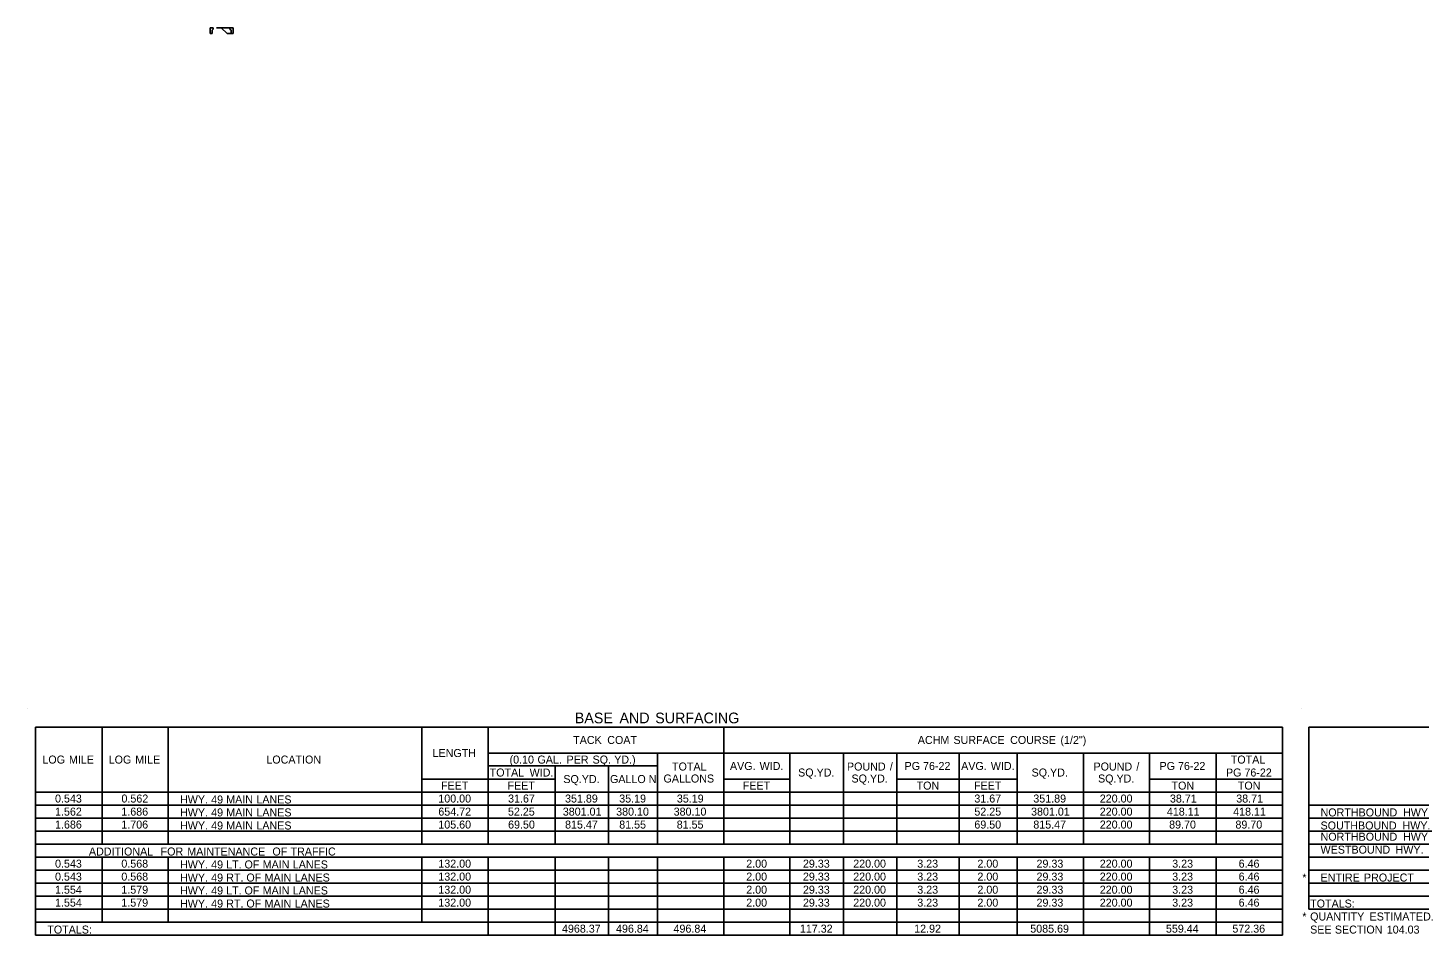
# Model space of a CAD drawing. Extents: x 107 to 7866, y 32 to 1473.
# Drawn here: x 2166 to 3209, y 716 to 1396 of the extents above; entities that cross this region are included whole.
import ezdxf

# ---------------------------------------------------------------- set-up
doc = ezdxf.new("R2010")
doc.units = 0
doc.layers.add('Default', color=7, linetype='Continuous')
doc.layers.add('R_No Plot', color=7, linetype='Continuous')

msp = doc.modelspace()

# ---------------------------------------------------------------- linework, layer by layer
at = {"layer": 'Default'}
for p, q in [((2166.5, 885.8), (2166.5, 885.8)), ((3120.9, 885.8), (3120.9, 885.8)), ((2172.3, 872.1), (3106.9, 872.1)), ((2172.3, 716.1), (2172.3, 872.1)), ((2172.3, 716.1), (2172.3, 872.1)), ((2222.1, 784.4), (2222.1, 872.1)), ((2271.8, 784.4), (2271.8, 872.1)), ((2271.8, 784.4), (2271.8, 872.1)), ((2461.9, 784.4), (2461.9, 872.1)), ((2511.6, 784.4), (2511.6, 872.1)), ((2688.1, 784.4), (2688.1, 872.1)), ((3106.9, 716.1), (3106.9, 872.1)), ((3126.7, 872.1), (3713.7, 872.1)), ((3126.7, 735.6), (3126.7, 872.1)), ((3126.7, 735.6), (3126.7, 872.1)), ((2511.6, 852.6), (3106.9, 852.6)), ((2638.4, 784.4), (2638.4, 852.6)), ((2737.8, 852.6), (2777.8, 852.6)), ((2737.8, 784.4), (2737.8, 852.6)), ((2777.8, 784.4), (2777.8, 852.6)), ((2817.8, 784.4), (2817.8, 852.6)), ((2864.6, 784.4), (2864.6, 852.6)), ((2908, 852.6), (2957.7, 852.6)), ((2908, 784.4), (2908, 852.6)), ((2957.7, 784.4), (2957.7, 852.6)), ((3007.4, 784.4), (3007.4, 852.6)), ((3057.2, 784.4), (3057.2, 852.6)), ((3106.9, 784.4), (3106.9, 852.6)), ((2511.6, 842.9), (2638.4, 842.9)), ((2561.9, 784.4), (2561.9, 842.9)), ((2601.8, 784.4), (2601.8, 842.9)), ((2461.9, 833.1), (2561.9, 833.1)), ((2511.6, 784.4), (2511.6, 833.1)), ((2561.9, 784.4), (2561.9, 833.1)), ((2688.1, 833.1), (2737.8, 833.1)), ((2688.1, 784.4), (2688.1, 833.1)), ((2737.8, 784.4), (2737.8, 833.1)), ((2817.8, 833.1), (2908, 833.1)), ((2864.6, 784.4), (2864.6, 833.1)), ((2908, 784.4), (2908, 833.1)), ((3007.4, 833.1), (3106.9, 833.1)), ((2172.3, 823.4), (3106.9, 823.4)), ((2172.3, 813.6), (3106.9, 813.6)), ((2222.1, 784.4), (2222.1, 823.4)), ((2461.9, 784.4), (2461.9, 823.4)), ((2561.9, 823.4), (2601.8, 823.4)), ((2601.8, 823.4), (2737.8, 823.4)), ((2601.8, 784.4), (2601.8, 823.4)), ((2638.4, 784.4), (2638.4, 823.4)), ((2737.8, 823.4), (2908, 823.4)), ((2777.8, 784.4), (2777.8, 823.4)), ((2817.8, 784.4), (2817.8, 823.4)), ((2908, 823.4), (3106.9, 823.4)), ((2957.7, 784.4), (2957.7, 823.4)), ((3007.4, 784.4), (3007.4, 823.4)), ((3057.2, 784.4), (3057.2, 823.4)), ((3126.7, 813.6), (3713.7, 813.6)), ((2172.3, 803.9), (3106.9, 803.9)), ((3126.7, 803.9), (3713.7, 803.9)), ((2172.3, 794.1), (3106.9, 794.1)), ((3126.7, 794.1), (3713.7, 794.1)), ((2172.3, 784.4), (2561.9, 784.4)), ((2172.3, 784.4), (3106.9, 784.4)), ((2561.9, 784.4), (2688.1, 784.4)), ((2688.1, 784.4), (2908, 784.4)), ((2908, 784.4), (2957.7, 784.4)), ((2957.7, 784.4), (3057.2, 784.4)), ((3057.2, 784.4), (3106.9, 784.4)), ((3126.7, 784.4), (3713.7, 784.4)), ((2172.3, 774.6), (3106.9, 774.6)), ((2222.1, 725.9), (2222.1, 774.6)), ((2222.1, 725.9), (2222.1, 774.6)), ((2271.8, 725.9), (2271.8, 774.6)), ((2271.8, 725.9), (2271.8, 774.6)), ((2461.9, 725.9), (2461.9, 774.6)), ((2461.9, 725.9), (2461.9, 774.6)), ((2511.6, 716.1), (2511.6, 774.6)), ((2511.6, 716.1), (2511.6, 774.6)), ((2561.9, 716.1), (2561.9, 774.6)), ((2561.9, 716.1), (2561.9, 774.6)), ((2601.8, 725.9), (2601.8, 774.6)), ((2601.8, 716.1), (2601.8, 774.6)), ((2638.4, 725.9), (2638.4, 774.6)), ((2638.4, 716.1), (2638.4, 774.6)), ((2688.1, 716.1), (2688.1, 774.6)), ((2688.1, 716.1), (2688.1, 774.6)), ((2737.8, 716.1), (2737.8, 774.6)), ((2737.8, 716.1), (2737.8, 774.6)), ((2777.8, 716.1), (2777.8, 774.6)), ((2777.8, 716.1), (2777.8, 774.6)), ((2817.8, 716.1), (2817.8, 774.6)), ((2817.8, 716.1), (2817.8, 774.6)), ((2864.6, 716.1), (2864.6, 774.6)), ((2864.6, 716.1), (2864.6, 774.6)), ((2908, 716.1), (2908, 774.6)), ((2908, 716.1), (2908, 774.6)), ((2957.7, 716.1), (2957.7, 774.6)), ((2957.7, 716.1), (2957.7, 774.6)), ((3007.4, 716.1), (3007.4, 774.6)), ((3007.4, 716.1), (3007.4, 774.6)), ((3057.2, 716.1), (3057.2, 774.6)), ((3057.2, 716.1), (3057.2, 774.6)), ((3106.9, 716.1), (3106.9, 774.6)), ((3126.7, 774.6), (3713.7, 774.6)), ((2172.3, 764.9), (3106.9, 764.9)), ((3126.7, 764.9), (3713.7, 764.9)), ((2172.3, 755.1), (3106.9, 755.1)), ((3126.7, 755.1), (3713.7, 755.1)), ((2172.3, 745.4), (3106.9, 745.4)), ((3126.7, 745.4), (3713.7, 745.4)), ((2172.3, 735.6), (3106.9, 735.6)), ((3126.7, 735.6), (3713.7, 735.6)), ((2172.3, 725.9), (3106.9, 725.9)), ((2172.3, 716.1), (3106.9, 716.1))]:
    msp.add_line(p, q, dxfattribs=at)
at = {"layer": 'R_No Plot'}
for p, q in [((2303.2, 1396.1), (2305.5, 1396.1)), ((2303.2, 1396.1), (2303.2, 1394.3)), ((2303.2, 1394.3), (2303.2, 1391.7)), ((2303.2, 1391.7), (2304.7, 1391.7)), ((2304.7, 1394.3), (2305.5, 1395.1)), ((2304.7, 1391.7), (2304.7, 1394.3)), ((2305.5, 1396.1), (2305.5, 1395.1)), ((2320.3, 1396.1), (2307.9, 1396.1)), ((2315.8, 1391.7), (2311.4, 1396.1)), ((2318.8, 1391.7), (2315.8, 1391.7)), ((2318, 1396.1), (2318, 1395.1)), ((2318.8, 1394.3), (2318, 1395.1)), ((2318.8, 1391.7), (2318.8, 1394.3)), ((2320.3, 1391.7), (2318.8, 1391.7)), ((2320.3, 1396.1), (2320.3, 1394.3)), ((2320.3, 1394.3), (2320.3, 1391.7))]:
    msp.add_line(p, q, dxfattribs=at)
msp.add_lwpolyline([(2315.8, 1391.7), (2311.4, 1396.1), (2318, 1396.1), (2318, 1395.1), (2318.8, 1394.3), (2318.8, 1391.7)], close=True, dxfattribs=at)

# ---------------------------------------------------------------- texts
at = {"layer": 'Default'}
for s, height, p in [('BASE', 8, (2576.5, 874.9)), (' AND', 8, (2607, 874.9)), (' SURFACING', 8, (2633.8, 874.9)), (' (1/2")', 6, (2938.3, 859.4)), ('LENGTH', 6, (2469.9, 849.6)), ('TACK', 6, (2575.3, 859.4)), (' COAT', 6, (2598.6, 859.4)), ('ACHM', 6, (2833.6, 859.4)), (' SURFACE', 6, (2858.1, 859.4)), (' COURSE', 6, (2900.6, 859.4)), ('LOG', 6, (2177.4, 844.7)), (' MILE', 6, (2195.1, 844.7)), ('LOG', 6, (2227.1, 844.7)), (' MILE', 6, (2244.8, 844.7)), ('LOCATION', 6, (2345.3, 844.7)), ('(0.10', 6, (2527.6, 844.7)), (' GAL.', 6, (2546.3, 844.7)), (' PER', 6, (2568.1, 844.7)), (' SQ.', 6, (2587.6, 844.7)), (' YD.)', 6, (2603.8, 844.7)), ('TOTAL', 6, (2649.4, 839.5)), ('AVG.', 6, (2692.8, 839.9)), (' WID.', 6, (2712.8, 839.9)), ('POUND', 6, (2780.5, 839.5)), (' /', 6, (2810.4, 839.5)), ('PG', 6, (2823.7, 839.9)), (' 76-22', 6, (2835.3, 839.9)), ('AVG.', 6, (2866.1, 839.9)), (' WID.', 6, (2886.1, 839.9)), ('POUND', 6, (2965.3, 839.5)), (' /', 6, (2995.2, 839.5)), ('PG', 6, (3014.8, 839.9)), (' 76-22', 6, (3026.4, 839.9)), ('TOTAL', 6, (3068.2, 844.7)), ('TOTAL', 6, (2512.7, 835)), (' WID.', 6, (2540.4, 835)), ('SQ.YD.', 6, (2567.9, 830.1)), ('GALLO', 6, (2602.9, 830.1)), ('N', 6, (2631.9, 830.1)), ('GALLONS', 6, (2643, 830.5)), ('SQ.YD.', 6, (2743.9, 835)), ('SQ.YD.', 6, (2783.9, 830.5)), ('SQ.YD.', 6, (2918.9, 835)), ('SQ.YD.', 6, (2968.7, 830.5)), ('PG', 6, (3064.6, 835)), (' 76-22', 6, (3076.2, 835)), ('FEET', 6, (2476.2, 825.2)), ('FEET', 6, (2526.1, 825.2)), ('FEET', 6, (2702.4, 825.2)), ('TON', 6, (2832.7, 825.2)), ('FEET', 6, (2875.7, 825.2)), ('TON', 6, (3023.8, 825.2)), ('TON', 6, (3073.5, 825.2)), ('0.543', 6, (2186.9, 815.5)), ('0.562', 6, (2236.7, 815.5)), ('HWY.', 6, (2280.6, 814.8)), (' 49', 6, (2301.7, 814.8)), (' MAIN', 6, (2313, 814.8)), (' LANES', 6, (2335.6, 814.8)), ('100.00', 6, (2474.2, 815.5)), ('31.67', 6, (2526.5, 815.5)), ('351.89', 6, (2569.2, 815.5)), ('35.19', 6, (2609.8, 815.5)), ('35.19', 6, (2653, 815.5)), ('31.67', 6, (2876, 815.5)), ('351.89', 6, (2920.2, 815.5)), ('220.00', 6, (2970, 815.5)), ('38.71', 6, (3022.6, 815.5)), ('38.71', 6, (3072.3, 815.5)), ('1.562', 6, (2186.9, 805.7)), ('1.686', 6, (2236.6, 805.7)), ('HWY.', 6, (2280.6, 805.1)), (' 49', 6, (2301.7, 805.1)), (' MAIN', 6, (2313, 805.1)), (' LANES', 6, (2335.6, 805.1)), ('654.72', 6, (2474.2, 805.7)), ('52.25', 6, (2526.4, 805.7)), ('3801.01', 6, (2567.5, 805.7)), ('380.10', 6, (2607.5, 805.7)), ('380.10', 6, (2650.6, 805.7)), ('52.25', 6, (2876, 805.7)), ('3801.01', 6, (2918.5, 805.7)), ('220.00', 6, (2970, 805.7)), ('418.11', 6, (3020.3, 805.7)), ('418.11', 6, (3070, 805.7)), ('NORTHBOUND', 6, (3135.5, 805.1)), (' HWY.', 6, (3195.1, 805.1)), ('1.686', 6, (2186.9, 796)), ('1.706', 6, (2236.6, 796)), ('HWY.', 6, (2280.6, 795.3)), (' 49', 6, (2301.7, 795.3)), (' MAIN', 6, (2313, 795.3)), (' LANES', 6, (2335.6, 795.3)), ('105.60', 6, (2474.2, 796)), ('69.50', 6, (2526.5, 796)), ('815.47', 6, (2569.2, 796)), ('81.55', 6, (2609.8, 796)), ('81.55', 6, (2652.9, 796)), ('69.50', 6, (2876, 796)), ('815.47', 6, (2920.2, 796)), ('220.00', 6, (2970, 796)), ('89.70', 6, (3022, 796)), ('89.70', 6, (3071.7, 796)), ('SOUTHBOUND', 6, (3135.5, 795.3)), ('NORTHBOUND', 6, (3135.5, 786.9)), (' HWY.', 6, (3194.7, 795.3)), (' HWY.', 6, (3195.1, 786.9)), ('WESTBOUND', 6, (3135.5, 777.2)), (' HWY.', 6, (3189.5, 777.2)), ('0.543', 6, (2186.9, 766.7)), ('ADDITIONAL', 6, (2212.3, 775.8)), ('0.568', 6, (2236.6, 766.7)), (' FOR', 6, (2263.8, 775.8)), ('HWY.', 6, (2280.6, 766.1)), (' MAINTENANCE', 6, (2283.8, 775.8)), (' 49', 6, (2301.7, 766.1)), (' LT.', 6, (2313, 766.1)), (' OF', 6, (2326.7, 766.1)), (' MAIN', 6, (2340.3, 766.1)), (' OF', 6, (2347.6, 775.8)), (' TRAFFIC', 6, (2361.2, 775.8)), (' LANES', 6, (2362.9, 766.1)), ('132.00', 6, (2474.2, 766.7)), ('2.00', 6, (2705, 766.7)), ('29.33', 6, (2747.5, 766.7)), ('220.00', 6, (2785.2, 766.7)), ('3.23', 6, (2833.2, 766.7)), ('2.00', 6, (2878.3, 766.7)), ('29.33', 6, (2922.6, 766.7)), ('220.00', 6, (2970, 766.7)), ('3.23', 6, (3024.3, 766.7)), ('6.46', 6, (3074.1, 766.7)), ('0.543', 6, (2186.9, 757)), ('0.568', 6, (2236.6, 757)), ('HWY.', 6, (2280.6, 756.3)), (' 49', 6, (2301.7, 756.3)), (' RT.', 6, (2313, 756.3)), (' OF', 6, (2328.1, 756.3)), (' MAIN', 6, (2341.7, 756.3)), (' LANES', 6, (2364.3, 756.3)), ('132.00', 6, (2474.2, 757)), ('2.00', 6, (2705, 757)), ('29.33', 6, (2747.5, 757)), ('220.00', 6, (2785.2, 757)), ('3.23', 6, (2833.2, 757)), ('2.00', 6, (2878.3, 757)), ('29.33', 6, (2922.6, 757)), ('220.00', 6, (2970, 757)), ('3.23', 6, (3024.3, 757)), ('6.46', 6, (3074.1, 757)), ('*', 6, (3121.8, 756.3)), ('ENTIRE', 6, (3135.5, 756.3)), (' PROJECT', 6, (3165.8, 756.3)), ('1.554', 6, (2186.9, 747.2)), ('1.579', 6, (2236.6, 747.2)), ('HWY.', 6, (2280.6, 746.6)), (' 49', 6, (2301.7, 746.6)), (' LT.', 6, (2313, 746.6)), (' OF', 6, (2326.7, 746.6)), (' MAIN', 6, (2340.3, 746.6)), (' LANES', 6, (2362.9, 746.6)), ('132.00', 6, (2474.2, 747.2)), ('2.00', 6, (2705, 747.2)), ('29.33', 6, (2747.5, 747.2)), ('220.00', 6, (2785.2, 747.2)), ('3.23', 6, (2833.2, 747.2)), ('2.00', 6, (2878.3, 747.2)), ('29.33', 6, (2922.6, 747.2)), ('220.00', 6, (2970, 747.2)), ('3.23', 6, (3024.3, 747.2)), ('6.46', 6, (3074.1, 747.2)), ('1.554', 6, (2186.9, 737.5)), ('1.579', 6, (2236.6, 737.5)), ('HWY.', 6, (2280.6, 736.8)), (' 49', 6, (2301.7, 736.8)), (' RT.', 6, (2313, 736.8)), (' OF', 6, (2328.1, 736.8)), (' MAIN', 6, (2341.7, 736.8)), (' LANES', 6, (2364.3, 736.8)), ('132.00', 6, (2474.2, 737.5)), ('2.00', 6, (2705, 737.5)), ('29.33', 6, (2747.5, 737.5)), ('220.00', 6, (2785.2, 737.5)), ('3.23', 6, (2833.2, 737.5)), ('2.00', 6, (2878.3, 737.5)), ('29.33', 6, (2922.6, 737.5)), ('220.00', 6, (2970, 737.5)), ('3.23', 6, (3024.3, 737.5)), ('6.46', 6, (3074.1, 737.5)), ('TOTALS:', 6, (3127.7, 736.8)), ('*', 6, (3121.8, 727.1)), ('QUANTITY', 6, (3127.7, 727.1)), (' ESTIMATED.', 6, (3170, 727.1)), ('TOTALS:', 6, (2181.1, 717.3)), ('4968.37', 6, (2566.9, 718)), ('496.84', 6, (2607.4, 718)), ('496.84', 6, (2650.5, 718)), ('117.32', 6, (2745.2, 718)), ('12.92', 6, (2830.9, 718)), ('5085.69', 6, (2917.9, 718)), ('559.44', 6, (3019.6, 718)), ('572.36', 6, (3069.4, 718)), ('SEE', 6, (3127.7, 717.3)), (' SECTION', 6, (3144, 717.3)), (' 104.03', 6, (3182.9, 717.3))]:
    msp.add_text(s, height=height, dxfattribs=at).set_placement(p)

doc.saveas('drawing.dxf')
